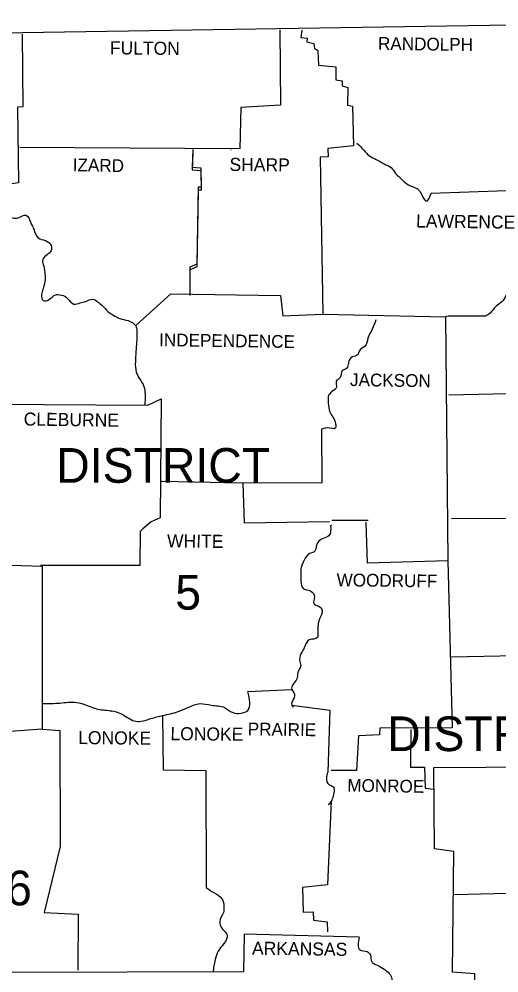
# Model space of a CAD drawing. Extents: x -17742 to 32032, y -17264 to 5867.
# Drawn here: x -16002 to -15135, y 4141 to 5867 of the extents above; entities that cross this region are included whole.
import ezdxf

# ---------------------------------------------------------------- set-up
doc = ezdxf.new("R2010")
doc.units = 0
for name, color, linetype in [('1', 7, 'Continuous'), ('2', 7, 'Continuous'), ('3', 7, 'Continuous')]:
    doc.layers.add(name, color=color, linetype=linetype)

msp = doc.modelspace()

# ---------------------------------------------------------------- linework, layer by layer
at = {"layer": '1'}
msp.add_line((-15436.7, 4960.3), (-15371.2, 4960.3), dxfattribs=at)
for points in [[(-17667.8, 5841.4), (-16777.9, 5840.9), (-15996.9, 5842.5), (-15075.6, 5856.8), (-14648.6, 5866.7)], [(-15996.9, 5839.2), (-15995.8, 5708.2), (-16005.2, 5707.7), (-16003.5, 5570.7), (-16042.1, 5565.2), (-16038.8, 5528.3), (-16025.5, 5511.2), (-16026.6, 5467.7), (-16101.5, 5465), (-16104.2, 5397.8), (-16172.5, 5395.6), (-16175.8, 5314.2), (-16171.9, 5307.6), (-16170.3, 5177.7), (-16052.5, 5170), (-16054.2, 4880), (-15960.6, 4877.2), (-15960.6, 4582.2), (-16034.4, 4576.7), (-16039.9, 4511.8), (-16163.7, 4511.2)], [(-15530.8, 5847.5), (-15529.7, 5711), (-15601.2, 5707.1), (-15603.4, 5632.3), (-16001.3, 5634.5)], [(-15491.2, 5846.9), (-15492.8, 5833.7), (-15481.8, 5832.1), (-15482.3, 5825.5), (-15469.7, 5822.7), (-15468.6, 5813.9), (-15462.5, 5810.1), (-15460.9, 5783.6), (-15429.5, 5780.3), (-15429.5, 5756.7), (-15418, 5755), (-15418, 5745.7), (-15408, 5742.9), (-15408.6, 5711), (-15399.8, 5709.3), (-15397.6, 5637.2), (-15444.4, 5632.8), (-15443.8, 5617.4), (-15458.1, 5616.9), (-15453.2, 5332.9), (-15231.4, 5327.9), (-15227.5, 4886.6), (-15372.3, 4882.7), (-15375, 4957)], [(-15688.2, 5630.6), (-15689.3, 5598.7), (-15673.9, 5597.6), (-15673.3, 5562.4), (-15678.8, 5562.4), (-15681, 5423.7), (-15693.7, 5418.2), (-15693.7, 5372)], [(-15688.2, 5625.7), (-15689.3, 5593.8), (-15673.9, 5592.7), (-15673.3, 5557.4), (-15678.8, 5557.4), (-15681, 5418.8), (-15693.7, 5413.3), (-15693.7, 5367)], [(-15619.4, 5629.5), (-15618.8, 5630.1)], [(-15257.3, 5551.9), (-15053.1, 5559.1)], [(-15790.5, 5313.1), (-15727.8, 5369.8), (-15529.7, 5367), (-15525.8, 5330.2), (-15453.7, 5332.9)], [(-15159.3, 5329.1), (-15226.4, 5329.1), (-15231.4, 5327.9)], [(-14718.5, 5198.1), (-15225.3, 5186.5)], [(-16052.5, 5170), (-15769.6, 5168.3), (-15745.4, 5179.9), (-15747.1, 4964.7), (-15763.6, 4957.6), (-15778.4, 4944.9), (-15783.4, 4940), (-15783.9, 4878.3), (-15963.9, 4878.3)], [(-15455.9, 5124.9), (-15454.8, 5028), (-15597.9, 5027.5), (-15744.9, 5030.2)], [(-15597.9, 5027.5), (-15595.7, 4955.4), (-15441.1, 4958.1)], [(-15220.9, 4963.6), (-15008.5, 4964.7), (-15007.9, 4972.4), (-14934.2, 4977.9), (-14934.2, 4966.4), (-14613.9, 4975.2)], [(-15436.7, 4951), (-15439.4, 4950.4)], [(-15227.5, 4886.6), (-15219.3, 4585), (-15350.3, 4584.4), (-15350.8, 4572.3), (-15388.8, 4570.1), (-15392.1, 4507.4), (-15438.3, 4507.4)], [(-15220.9, 4713.2), (-14783.9, 4722)], [(-15589.1, 4650.5), (-15509.3, 4654.3)], [(-15509.3, 4625.7), (-15440.5, 4616.9), (-15444.4, 4504.6)], [(-15743.2, 4607.5), (-15742.1, 4509), (-15664.5, 4507.4), (-15664, 4296)], [(-15960.6, 4582.2), (-15928.7, 4580), (-15928.1, 4369.8), (-15956.8, 4250.4), (-15895.7, 4247.6), (-15896.2, 4146.3)], [(-15294.1, 4581.7), (-15294.7, 4513.4), (-15269.4, 4513.4), (-15268.3, 4475.5), (-15252.3, 4473.8)], [(-15220.9, 4025.3), (-15178, 4028), (-15178.6, 4139.7), (-15218.7, 4142.5), (-15216.5, 4361), (-15251.2, 4365.9), (-15252.3, 4512.9), (-14782.8, 4516.2)], [(-15438.3, 4451.8), (-15444.9, 4301), (-15490.1, 4296), (-15489, 4251.5), (-15470.8, 4252), (-15470.2, 4236.6), (-15445.5, 4233.8), (-15444.9, 4215.7)], [(-15215.4, 4283.4), (-14905, 4291.1)], [(-15387.7, 4205.8), (-15595.7, 4211.3), (-15596.8, 4143.6), (-16017.8, 4141.9)]]:
    msp.add_lwpolyline(points, dxfattribs=at)
for points in [[(-15391.5, 5642.2), (-15379.4, 5629.5), (-15369, 5619.1), (-15356.9, 5613), (-15342.6, 5604.8), (-15329.9, 5598.2), (-15321.6, 5587.7), (-15310.1, 5576.2), (-15298.5, 5566.8), (-15280.4, 5558), (-15274.3, 5548.6), (-15266.1, 5537.1), (-15257.3, 5551.9)], [(-15054.7, 5558.5), (-15063, 5545.3), (-15069.6, 5529.9), (-15082.8, 5512.3), (-15092.7, 5495.3), (-15094.3, 5483.7), (-15102.1, 5468.3), (-15106.5, 5452.9), (-15111.4, 5439.7), (-15111.4, 5425.9), (-15107.6, 5412.2), (-15108.7, 5399.5), (-15116.9, 5393.4), (-15119.1, 5377.5), (-15122.4, 5366.5), (-15129.6, 5355.5), (-15140, 5347.2), (-15151, 5334.6), (-15159.3, 5329.1)], [(-16025.5, 5511.2), (-16003.5, 5507.4), (-15990.3, 5512.3), (-15981, 5498), (-15976, 5487), (-15967.8, 5471), (-15954.6, 5466.1), (-15944.6, 5457.3), (-15944.6, 5447.9), (-15953.4, 5439.1), (-15960.1, 5430.3), (-15957.9, 5419.9), (-15955.7, 5405.5), (-15955.7, 5391.8), (-15959, 5379.1), (-15961.7, 5367.6), (-15959, 5357.7), (-15948.5, 5359.3), (-15937.5, 5367.6), (-15925.9, 5367.6), (-15914.9, 5361.5), (-15903.4, 5351.1), (-15891.8, 5353.3), (-15882.5, 5356), (-15869.2, 5359.9), (-15859.9, 5354.9), (-15851.6, 5348.3), (-15841.7, 5337.9), (-15832.4, 5331.3), (-15820.3, 5325.2), (-15805.4, 5321.3), (-15791.6, 5312), (-15789.4, 5296), (-15790, 5282.3), (-15791.1, 5265.2), (-15792.2, 5246.5), (-15790.5, 5228.3), (-15784.5, 5216.2), (-15776.8, 5201.9), (-15774.6, 5188.7), (-15775.1, 5167.8)], [(-15357.4, 5323), (-15364, 5305.9), (-15371.7, 5289.4), (-15376.7, 5275.1), (-15387.1, 5266.9), (-15390.4, 5259.2), (-15399.8, 5255.9), (-15406.9, 5244.8), (-15410.3, 5234.9), (-15418, 5230.5), (-15421.8, 5218.4), (-15429, 5211.8), (-15428.4, 5200.8), (-15436.7, 5193.1), (-15443.3, 5184.3), (-15443.3, 5172.2), (-15440.5, 5156.2), (-15435, 5146.9), (-15430.1, 5134.8), (-15430.6, 5127.1), (-15444.4, 5127.1), (-15455.9, 5124.9)], [(-15439.4, 4950.4), (-15442.2, 4932.2), (-15452.6, 4927.3), (-15464.7, 4915.2), (-15467.5, 4904.2), (-15477.4, 4899.8), (-15486.7, 4888.2), (-15492.8, 4872.3), (-15492.8, 4855.7), (-15489, 4837), (-15475.2, 4832.1), (-15468.6, 4821.1), (-15469.7, 4809.5), (-15456.5, 4801.8), (-15454.3, 4795.2), (-15456.5, 4788.1), (-15462.5, 4767.7), (-15462, 4753.9), (-15463.1, 4747.9), (-15477.9, 4744), (-15486.7, 4729.2), (-15492.8, 4718.7), (-15495, 4704.9), (-15493.4, 4695), (-15497.8, 4687.3), (-15499.4, 4675.8), (-15504.9, 4665.9), (-15509.9, 4656.5), (-15504.4, 4645.5), (-15506, 4637.8), (-15509.3, 4625.7), (-15506.6, 4621.8)], [(-15959.5, 4628.5), (-15928.7, 4629.6), (-15898.4, 4630.7), (-15879.2, 4625.1), (-15857.1, 4618), (-15831.3, 4614.7), (-15813.1, 4607.5), (-15791.6, 4596.5), (-15764.1, 4601.5), (-15742.7, 4607), (-15714.6, 4614.1), (-15696.4, 4621.8), (-15675.5, 4628.5), (-15654.6, 4625.7), (-15630.9, 4621.3), (-15616.1, 4612.5), (-15589.1, 4616.3), (-15589.1, 4650.5)], [(-15444.4, 4504.6), (-15446.6, 4493.6), (-15442.2, 4482.1), (-15434.5, 4478.2), (-15433.4, 4467.2), (-15436.1, 4456.2), (-15438.3, 4451.8), (-15443.3, 4445.2)], [(-14817.5, 4383), (-14830.2, 4367), (-14848.9, 4376.9), (-14848.9, 4390.1), (-14846.1, 4403.9), (-14852.7, 4412.7), (-14864.3, 4408.9), (-14864.3, 4391.8), (-14865.4, 4375.3), (-14868.7, 4351.6), (-14861, 4344.5), (-14843.4, 4342.3), (-14830.7, 4339), (-14823, 4326.3), (-14823.6, 4310.9), (-14829.6, 4296), (-14838.4, 4283.9), (-14852.2, 4279.5), (-14863.2, 4286.7), (-14867.6, 4301), (-14872.6, 4313.6), (-14881.9, 4323), (-14891.8, 4312.5), (-14894, 4293.3), (-14893.5, 4276.8), (-14893.5, 4254.2), (-14879.2, 4239.3), (-14870.4, 4222.3), (-14873.1, 4206.9), (-14883.6, 4188.7), (-14888, 4172.8), (-14892.4, 4151.3), (-14891.8, 4127.6), (-14895.7, 4104.5), (-14903.4, 4089.1), (-14917.7, 4076.4), (-14927, 4068.2), (-14934.7, 4059.9), (-14938.6, 4043.4), (-14941.3, 4031.9), (-14951.8, 4018.1), (-14960.1, 4017), (-14966.7, 4022.5), (-14968.9, 4031.9), (-14968.9, 4041.2), (-14973.3, 4050.6), (-14987, 4054.4), (-14998, 4053.9), (-15003, 4046.2), (-14995.8, 4024.7), (-14993.1, 4011), (-14996.9, 3992.2), (-14994.7, 3990), (-15014.5, 3979.6), (-15030.5, 3977.9), (-15043.7, 3974.1), (-15056.4, 3965.8), (-15062.4, 3953.7), (-15071.2, 3943.8), (-15078.9, 3934.5), (-15089.4, 3930.1), (-15101, 3932.3), (-15116.4, 3933.9), (-15125.2, 3922.9), (-15122.4, 3906.9), (-15112, 3897.6), (-15096.5, 3893.2), (-15080.6, 3894.3), (-15065.2, 3895.9), (-15050.9, 3888.2), (-15053.6, 3873.4), (-15067.4, 3866.2), (-15087.7, 3864), (-15104.3, 3865.7), (-15124.1, 3861.3), (-15134, 3848.6), (-15128.5, 3829.3), (-15107, 3821.6), (-15097.1, 3803.5), (-15096.5, 3786.4), (-15103.7, 3763.8), (-15113.6, 3753.4), (-15132.9, 3749), (-15147.7, 3746.2), (-15149.9, 3720.9), (-15156.5, 3708.3), (-15168.1, 3704.4), (-15184.6, 3712.7), (-15194.5, 3716.5), (-15206.6, 3722), (-15222, 3731.4), (-15233.6, 3729.7), (-15230.3, 3705.5), (-15229.2, 3704.4), (-15216, 3686.2), (-15202.8, 3671.9), (-15196.7, 3654.9)], [(-15664, 4296), (-15650.2, 4286.7), (-15635.9, 4275.7), (-15632, 4260.8), (-15633.1, 4250.4), (-15637.5, 4241.6), (-15638.6, 4227.8), (-15632, 4217.9), (-15626, 4209.6), (-15632, 4194.8), (-15642.5, 4181), (-15648, 4165.6), (-15651.9, 4142.5)], [(-15387.7, 4205.8), (-15386, 4183.2), (-15372.8, 4179.9), (-15367.3, 4173.9), (-15364.6, 4161.2), (-15355.2, 4155.7), (-15342.6, 4148), (-15334.9, 4142.5), (-15329.3, 4133.7), (-15326, 4119.4), (-15317.2, 4110), (-15305.1, 4105.6), (-15296.3, 4095.2), (-15290.8, 4080.3), (-15282, 4073.7), (-15273.2, 4062.1), (-15268.8, 4057.2), (-15261.1, 4044), (-15253.4, 4037.4), (-15247.9, 4033.5), (-15239.1, 4030.8), (-15228.1, 4023.6), (-15220.9, 4012.6), (-15220.9, 4004.3), (-15223.7, 3991.7), (-15225.9, 3978.5), (-15227, 3963.6), (-15228.1, 3950.4), (-15223.1, 3939.4), (-15225.9, 3922.9), (-15231.4, 3914.1), (-15231.9, 3902), (-15233.6, 3883.8), (-15235.8, 3873.4), (-15240.7, 3856.3), (-15247.9, 3847.5)]]:
    msp.add_spline(points, degree=3, dxfattribs=at)

# ---------------------------------------------------------------- texts
at = {"layer": '2'}
for s, height, rotation, p in [('RANDOLPH', 23.11, 359.2583, (-15353.6, 5811.2)), ('FULTON', 23.66, 359.4996, (-15838.4, 5802.9)), ('IZARD', 23.11, 358.9258, (-15905.6, 5591.6)), ('SHARP', 23.66, 359.3905, (-15622.1, 5592.1)), ('LAWRENCE', 23.67, 359.2678, (-15284.8, 5489.8)), ('INDEPENDENCE', 23.108, 359.2187, (-15749.3, 5275.1)), ('JACKSON', 23.11, 359.1352, (-15404.2, 5203)), ('CLEBURNE', 23.66, 359.2535, (-15994.2, 5131.5)), ('WHITE', 23.67, 359.3139, (-15735, 4911.3)), ('WOODRUFF', 23.11, 359.2748, (-15428.4, 4840.9)), ('PRAIRIE', 23.11, 359.2116, (-15589.1, 4571.2)), ('LONOKE', 23.67, 359.4974, (-15895.7, 4555.3)), ('LONOKE', 23.67, 359.4974, (-15728.9, 4562.4)), ('MONROE', 23.11, 359.0331, (-15409.1, 4469.4)), ('ARKANSAS', 23.66, 359.2678, (-15581.4, 4174.4))]:
    msp.add_text(s, height=height, rotation=rotation, dxfattribs=at).set_placement(p)
at = {"layer": '3'}
for s, height, p in [('DISTRICT', 62.74, (-15935.3, 5028)), ('5', 62.7, (-15720.1, 4798.5)), ('DISTRICT', 62.74, (-15337.1, 4542.6)), ('DISTRICT 6', 62.74, (-16436.1, 4263.6))]:
    msp.add_text(s, height=height, dxfattribs=at).set_placement(p)

doc.saveas('drawing.dxf')
